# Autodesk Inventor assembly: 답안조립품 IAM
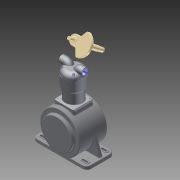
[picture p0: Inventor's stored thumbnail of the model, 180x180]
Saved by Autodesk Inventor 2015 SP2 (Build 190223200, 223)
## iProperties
Created: 2015-06
Part Number: 답안조립품 IAM
Document SubType Name: Assembly
Designer: Guest
Author: Guest
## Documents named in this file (5)
- C:\Users\Guest\Desktop\450606V1021\답안조립품 IAM.iam
- C:\Users\Guest\Desktop\450606V1021\본체.ipt
- C:\Users\Guest\Desktop\450606V1021\실린더헤드.ipt
- C:\Users\Guest\Desktop\450606V1021\메인 크랭크 축-구동부.ipt
- C:\Users\Guest\Desktop\450606V1021\실린더.ipt
